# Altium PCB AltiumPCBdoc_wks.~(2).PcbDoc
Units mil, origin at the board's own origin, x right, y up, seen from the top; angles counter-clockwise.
Board outline 1600 x 2600 mil, 2 copper layers (Top Layer, Bottom Layer); 20 components, 16 nets, 64 pads, 0 vias.
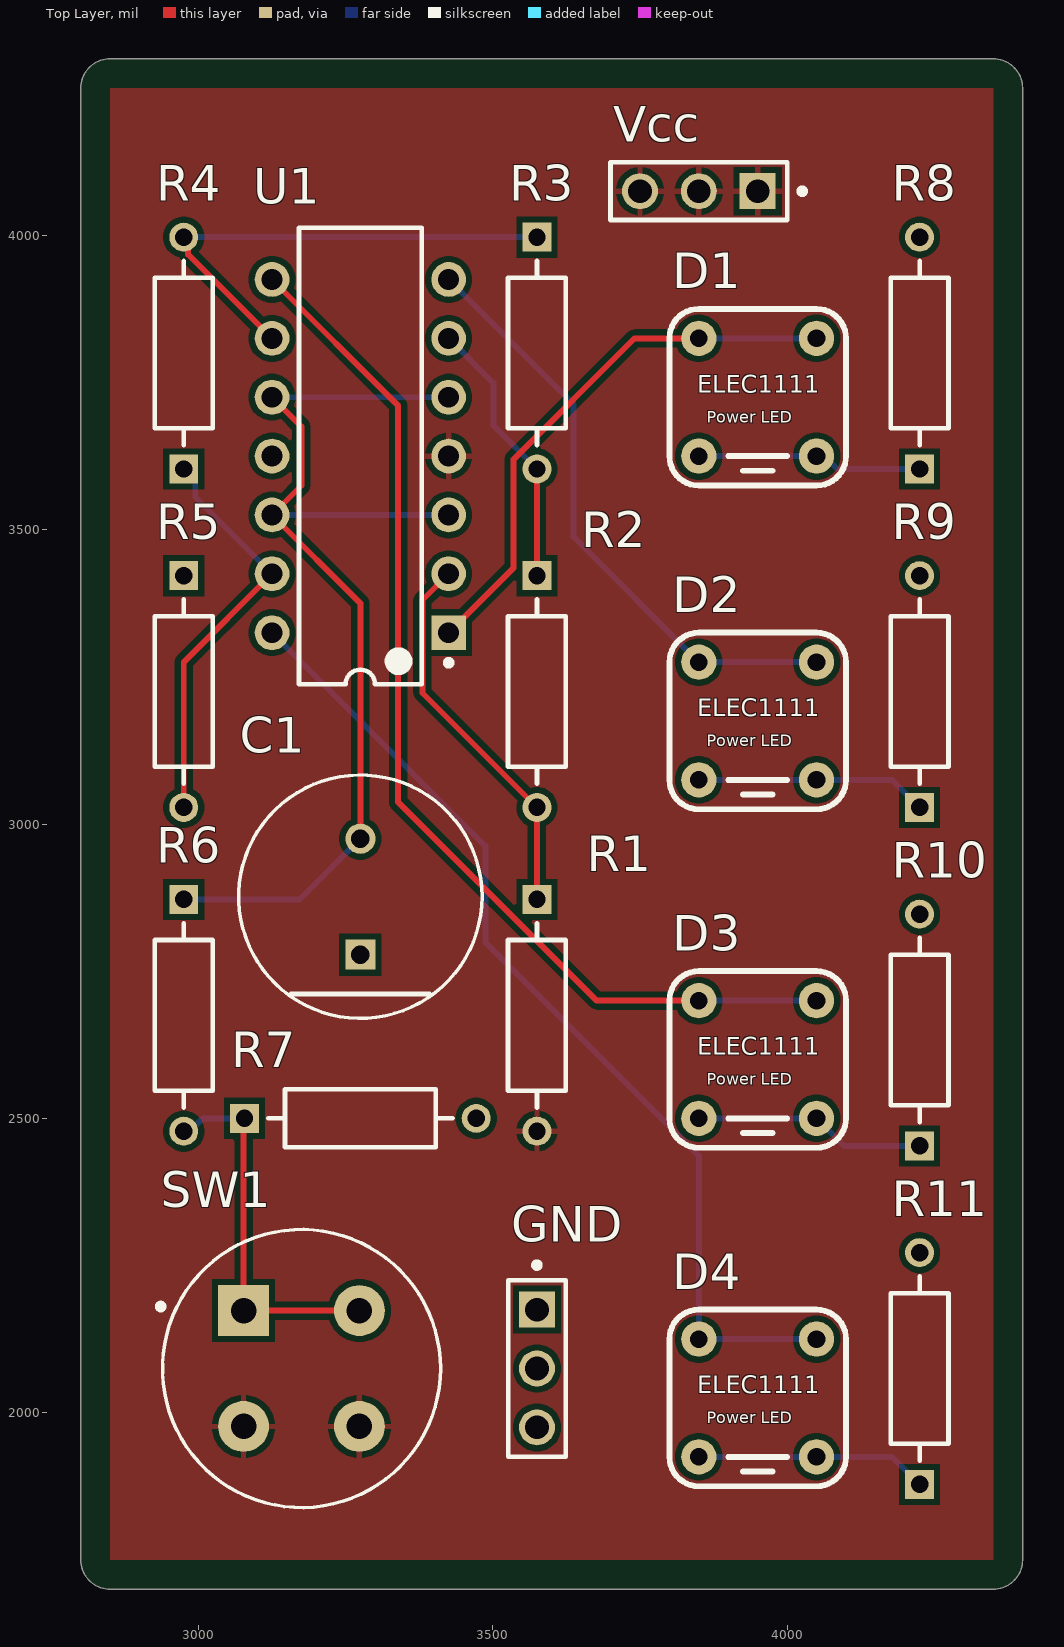
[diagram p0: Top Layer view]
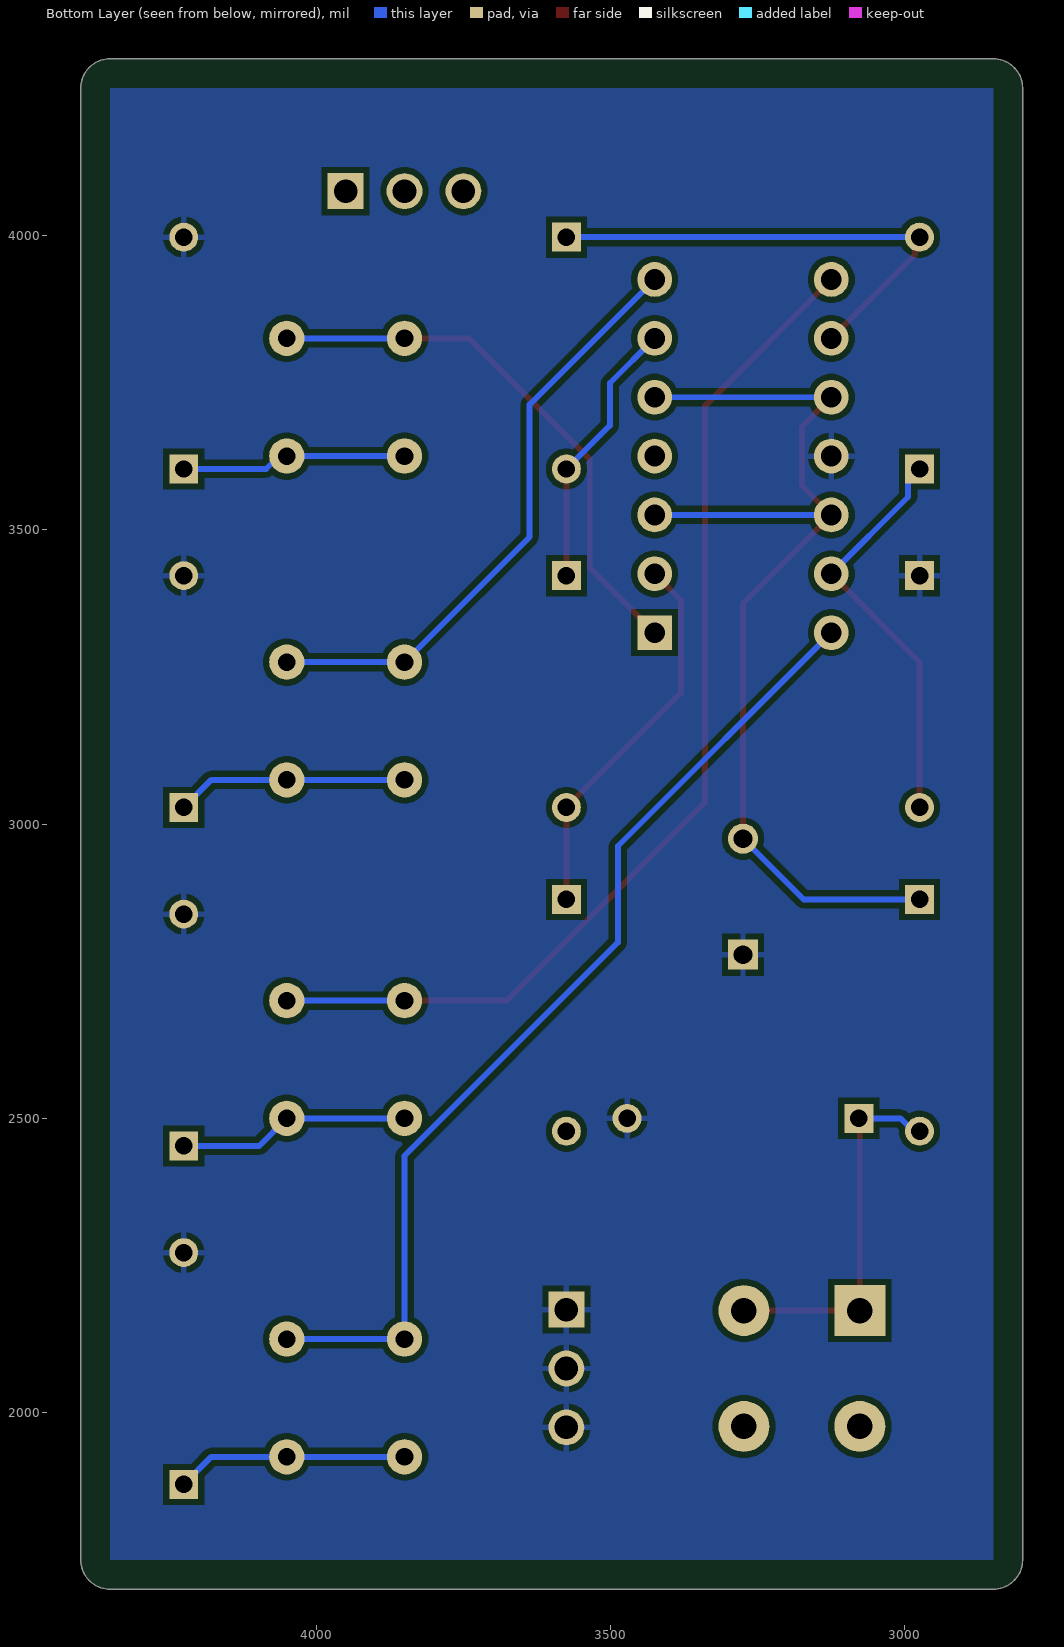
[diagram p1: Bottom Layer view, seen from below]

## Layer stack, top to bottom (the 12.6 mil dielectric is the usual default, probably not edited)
Top Solder: solder mask 0.4, Solder Resist, Dk 3.5
Top Layer: signal copper 1.4
Dielectric 1: dielectric 12.6, FR-4, Dk 4.8
Bottom Layer: signal copper 1.4
Bottom Solder: solder mask 0.4, Solder Resist, Dk 3.5

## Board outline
2800,1750 2800,4250 cw(c2850,4250) 2850,4300 4350,4300 cw(c4350,4250) 4400,4250 4400,1750 cw(c4350,1750) 4350,1700 2850,1700 cw(c2850,1750)

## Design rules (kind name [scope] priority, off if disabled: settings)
Clearance [All] p1: gap=10 ignorepadtopadclearanceinfootprint=FALSE except(0: Arc-Hole Track-Hole SMDPad-Hole THPad-Hole Via-Hole Fill-Hole Poly-Hole Region-Hole Text-Hole)
PolygonConnect [All] p1: connectstyle=Relief reliefconductorwidth=10 reliefentries=4 polygonreliefangle="90 Angle" airgapwidth=10
RoutingVias [All] p1: holewidth=28 width=50 viastyle="Through Hole" minholewidth=28 minwidth=50 maxholewidth=28 maxwidth=50
SolderMaskExpansion [All] p1: expansion=4 istentingtop=FALSE
Width [All] p1: maxlimit=10 minlimit=10 preferedwidth=10
30 further rules are at their usual default settings.

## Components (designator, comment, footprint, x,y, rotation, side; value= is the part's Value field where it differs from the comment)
C1 "ECA1CM102" FP-RAD-TH-D_10_0_5-L_16_1-MFG 3275,2876.57 r90 top
D1 "ELEC1111 Power LED" ELEC1111_PowerLED 3950,3725 r0 top
D2 "ELEC1111 Power LED" ELEC1111_PowerLED 3950,3175 r0 top
D3 "ELEC1111 Power LED" ELEC1111_PowerLED 3950,2600 r0 top
D4 "ELEC1111 Power LED" ELEC1111_PowerLED 3950,2025 r0 top
GND "22-28-4033" MOLX-22-28-4033_V 3575,2075 r270 top
R1 "MRS25000C1001FCT00" FP-MRS25-MFG 3575,2675 r270 top
R2 "MRS25000C1001FCT00" FP-MRS25-MFG 3575,3225 r270 top
R3 "MRS25000C1001FCT00" FP-MRS25-MFG 3575,3800 r270 top
R4 "MRS25000C1001FCT00" FP-MRS25-MFG 2975,3800 r90 top
R5 "MRS25000C1001FCT00" FP-MRS25-MFG 2975,3225 r270 top
R6 "MRS25000C1001FCT00" FP-MRS25-MFG 2975,2675 r270 top
R7 "MRS25000C1001FCT00" FP-MRS25-MFG 3275,2500 r0 top
R8 "MRS25000C1001FCT00" FP-MRS25-MFG 4225,3800 r90 top
R9 "MRS25000C1001FCT00" FP-MRS25-MFG 4225,3225 r90 top
R10 "MRS25000C1001FCT00" FP-MRS25-MFG 4225,2650 r90 top
R11 "MRS25000C1001FCT00" FP-MRS25-MFG 4225,2075 r90 top
SW1 "D6R40F1LFS" FP-D6R40F1LFS-MFG 3175,2075 r0 top
U1 "LM324N" N0014A 3275,3625 r180 top
Vcc "22-28-4033" MOLX-22-28-4033_V 3850,4075 r180 top

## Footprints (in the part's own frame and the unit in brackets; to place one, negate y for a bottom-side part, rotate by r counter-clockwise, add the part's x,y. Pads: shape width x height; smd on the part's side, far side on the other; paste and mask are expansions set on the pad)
ELEC1111_PowerLED [mil]
  round 60 hole 30: 1(-100,100) 2(100,100) 3(-100,-100) 4(100,-100)
  silkscreen extent -150,-150 150,150
FP-D6R40F1LFS-MFG [mm]
  rect 2.2x2.2 hole 1.1 paste-2539.97 mask+0: 1(-2.5,2.5)
  round 2.2 hole 1.1 paste-2539.97 mask+0: 2(2.5,2.5) 3(-2.5,-2.5) 4(2.5,-2.5)
  silkscreen extent -6.2,-6 6,6, body extent -6.1,-6.1 6.1,6.1, height 0.25
FP-MRS25-MFG [mm]
  rect 1.25x1.25 hole 0.75 paste-2539.97 mask+0: 1(-5,0)
  round 1.25 hole 0.75 paste-2539.97 mask+0: 2(5,0)
  silkscreen extent -3.98,-1.25 3.98,1.25, body extent -5.72,-1.35 5.72,1.35, height 0.25
FP-RAD-TH-D_10_0_5-L_16_1-MFG [mm]
  rect 1.3x1.3 hole 0.8 paste-2539.97 mask+0: 1(-2.5,0)
  round 1.3 hole 0.8 paste-2539.97 mask+0: 2(2.5,0)
  silkscreen extent -5.25,-5.25 5.25,5.25, body extent -5.35,-5.35 5.35,5.35, height 0.25
MOLX-22-28-4033_V [mm] "THD, 3-Leads, Body 7.62x2.49mm, Pitch 2.54mm"
  rect 1.55x1.55 hole 1.02: 1(-2.54,0)
  round 1.55 hole 1.02: 2(0,0) 3(2.54,0)
  silkscreen extent -4.58,-1.24 3.81,1.24, body extent -3.81,-1.24 3.81,1.24, height 8.38
N0014A [mm] "DIP, 14-Leads, Body 19.7x6.6mm, Pitch 2.54mm"
  rect 1.5x1.5 hole 0.9: 1(-3.81,7.62)
  round 1.5 hole 0.9: 2(-3.81,5.08) 3(-3.81,2.54) 4(-3.81,0) 5(-3.81,-2.54) 6(-3.81,-5.08) 7(-3.81,-7.62) 8(3.81,-7.62) 9(3.81,-5.08) 10(3.81,-2.54) 11(3.81,0) 12(3.81,2.54) 13(3.81,5.08) 14(3.81,7.62)
  silkscreen extent -3.94,-9.85 2.65,9.85, body extent -3.95,-9.85 3.95,9.85, height 5.08

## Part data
C1: library part CMP-05427-001524-1, "Aluminum Electrolytic Capacitors (Radial Lead Type) 1000uF ±20% 16V", Capacitance=1mF, Case/Package=Radial, Leakage Current=3uA, Max Operating Temperature=85°C, Min Operating Temperature=-40°C, Package Quantity=200, Ripple Current=680mA, Tolerance=20%, Voltage=16V
D1 D2 D3 D4: "An LED used in ELEC1111"
GND Vcc: library part CMP-1676-00001-5, "Male Header, Pitch 2.54 mm, 1 x 3 Position, Height 8.38 mm, Tail Length 3.18 mm, RoHS, Bulk", Colour=Black, Current Rating="4 A", Manufacturer=Molex, Max Operating Temperature="75 degC", Min Operating Temperature="0 degC", Package Quantity=1, Voltage Rating="250 V"
R1 R2 R3 R4 R5 R6 R7 R8 R9 R10 R11: library part CMP-02408-000051-1, "RES 1K OHM 0.6W 1% AXIAL", Case/Package=Axial, Max Operating Temperature=155°C, Max Power Dissipation=600mW, Min Operating Temperature=-55°C, Package Quantity=5000, Resistance=1kR, Resistance Tolerance=1%, Resistor Type="Metal Film", Temperature Coefficient=50ppm/°C, Voltage Rating=350V
SW1: library part CMP-10035-000005-1, "SWITCH PUSH SPST-NO 0.1A 32V", Actuator Color=Red, Contact Current Rating=100mA, Contact Resistance=100mR, Insulation Resistance=100GR, Max Operating Temperature=85°C, Max Voltage Rating (DC)=32V, Min Operating Temperature=-20°C, Operating Force=1.3N, Package Quantity=2500, Power Rating=3W, Voltage Rating (AC)=100V
U1: library part CMP-0055-00082-3, "Low Power Quad Operational Amplifier, 14-pin MDIP", Manufacturer="Texas Instruments", Package Reference=N0014A, PackageTopMarking=NSUZXYYTTE#*LM324N, PowerWise=N

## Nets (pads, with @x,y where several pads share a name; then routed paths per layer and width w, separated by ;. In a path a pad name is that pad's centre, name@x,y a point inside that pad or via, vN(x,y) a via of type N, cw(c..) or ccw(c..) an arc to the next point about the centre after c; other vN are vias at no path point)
+5: R1.2 SW1.3 SW1.4 U1.4 Vcc.1 Vcc.2 Vcc.3
GND: C1.1 GND.1 GND.2 GND.3 R5.1 R7.2 R8.2 R9.2 R10.2 R11.2 U1.11
NetD1_1: D1.1 D1.2 U1.1 | length 940
  Top Layer w10: U1.1 3535.39,3435.39 3535.39,3619.55 3740.84,3825 D1.1
  Bottom Layer w10: D1.1 D1.2
NetD1_3: D1.3 D1.4 R8.1 | length 384.1
  Bottom Layer w10: D1.3 D1.4 4063.53,3625 4085.38,3603.15 R8.1
NetD2_1: D2.1 D2.2 U1.7 | length 1026
  Bottom Layer w10: U1.7 3637.41,3712.59 3637.41,3487.59 D2.1 D2.2
NetD2_3: D2.3 D2.4 R9.1 | length 394.4
  Bottom Layer w10: D2.3 D2.4 4178.15,3075 R9.1
NetD3_1: D3.1 D3.2 U1.8 | length 1827
  Top Layer w10: U1.8 3339.28,3710.72 3339.28,3037.14 3676.42,2700 D3.1
  Bottom Layer w10: D3.1 D3.2
NetD3_3: D3.3 D3.4 R10.1 | length 394.4
  Bottom Layer w10: D3.3 D3.4 4096.85,2453.15 R10.1
NetD4_1: D4.1 D4.2 U1.14 | length 1700.3
  Bottom Layer w10: U1.14 3487.41,2962.59 3487.41,2798.95 3850,2436.36 D4.1 D4.2
NetD4_3: D4.3 D4.4 R11.1 | length 394.4
  Bottom Layer w10: D4.3 D4.4 4178.15,1925 R11.1
NetR1_1: R1.1 R2.2 U1.2 | length 652.2
  Top Layer w10: U1.2 3380.47,3380.47 3380.47,3222.68 R2.2 R1.1
NetR2_1: R2.1 R3.2 U1.6 | length 465.3
  Top Layer w10: R2.1 R3.2
  Bottom Layer w10: U1.6 3500.94,3749.06 3500.94,3677.21 R3.2
NetR3_1: R3.1 R4.2 U1.9 | length 834
  Top Layer w10: R4.2 2982.5,3989.35 2982.5,3967.5 U1.9
  Bottom Layer w10: R4.2 R3.1
NetR4_1: R4.1 R5.2 U1.13 | length 699.3
  Top Layer w10: R5.2 2975,3275 U1.13
  Bottom Layer w10: R4.1 2994.61,3583.54 2994.61,3555.39 U1.13
NetR6_2: R6.2 R7.1 SW1.1 SW1.2 | length 661.8
  Top Layer w10: R7.1@3058.54,2480.39 R7.1@3076.57,2498.43 ; R7.1 R7.1@3076.57,2498.43 ; SW1.2 SW1.1 R7.1@3076.57,2498.43
  Bottom Layer w10: R6.2 2985.61,2478.15 3007.46,2500 R7.1
Signal: C1.2 R6.1 U1.3 U1.5 U1.10 U1.12 | length 1796.3
  Top Layer w10: U1.10 3175,3675 3175,3575 U1.12 3275,3375 C1.2
  Bottom Layer w10: R6.1 3171.85,2871.85 C1.2 ; U1.12 U1.3 ; U1.10 U1.5

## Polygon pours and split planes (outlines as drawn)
+5 on Top Layer "+5_L01_P001" (solid, pour order 1): 2850,4250 2850,1750 4350,1750 4350,4250
GND on Bottom Layer "GND_L02_P003" (solid, pour order 3): 2850,4250 4350,4250 4350,1750 2850,1750

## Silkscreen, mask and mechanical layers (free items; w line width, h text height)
Mechanical 1:
  lines w10: 2800,1750 ccw(c2850,1750) 2850,1700 4350,1700 ccw(c4350,1750) 4400,1750 4400,4250 ccw(c4350,4250) 4350,4300 2850,4300 ccw(c2850,4250) 2800,4250 2800,4000 2800,1750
